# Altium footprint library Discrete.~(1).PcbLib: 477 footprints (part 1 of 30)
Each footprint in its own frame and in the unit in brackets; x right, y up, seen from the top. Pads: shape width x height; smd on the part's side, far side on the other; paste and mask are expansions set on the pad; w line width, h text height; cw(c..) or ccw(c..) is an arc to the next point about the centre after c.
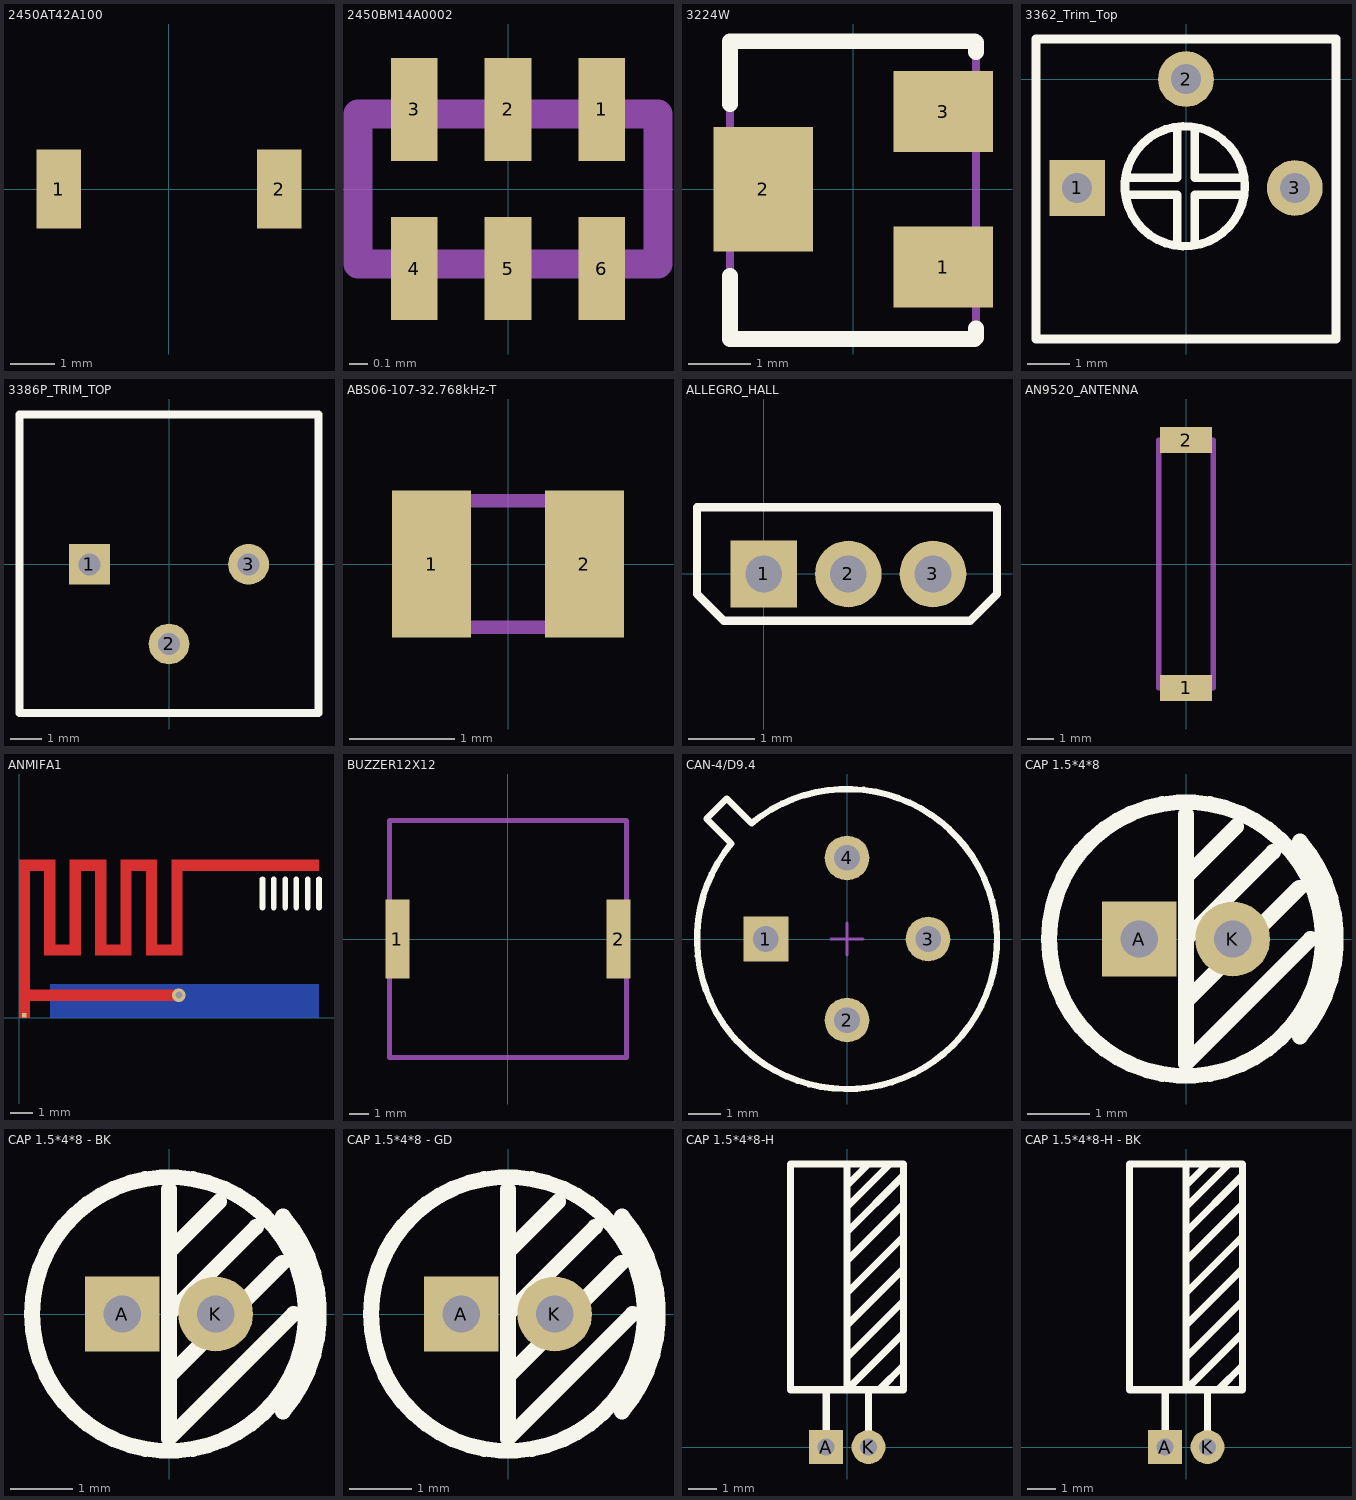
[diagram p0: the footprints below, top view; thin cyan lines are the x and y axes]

## 2450AT42A100 [mm]
pads (2):
  rect 1x1.8 smd: 1(-2.5,0) 2(2.5,0)
3D body: height 1.11, standoff 0, extent -2.1,-0.4 -1.5,0.4
3D body: height 1.1, standoff 0, extent -2.5,-1 2.5,1

## 2450BM14A0002 [mm] "Impedance Matched Balun Filter Integrated Passive for   Nordic’s nRF24L01 and nRF24L01+ Chipsets"
pads (6):
  rect 0.25x0.55 smd: 1(0.5,0.425) 2(0,0.425) 3(-0.5,0.425) 4(-0.5,-0.425) 5(0,-0.425) 6(0.5,-0.425)
Mechanical 13:
  lines w0.152: -0.8,-0.4 0.8,-0.4 0.8,0.4 -0.8,0.4 -0.8,-0.4
3D body: height 0.6, standoff 0, extent -0.8,-0.4 0.8,0.4

## 3224W [mm] "3224 - 4 mm SMD Trimpot"
height 5.1
pads (3):
  rect 1.6x1.3 smd: 1(1.45,-1.25) 3(1.45,1.25)
  rect 1.6x2 smd: 2(-1.45,0)
Top Overlay:
  lines w0.254: -1.98,-1.397 -1.98,-2.408 1.954,-2.408 1.975,-2.388 1.975,-2.235 ; -1.98,1.372 -1.98,2.383 1.954,2.383 1.975,2.362 1.975,2.21
Mechanical 13:
  lines w0.127: -1.98,2.383 1.975,2.383 ; -1.98,-2.408 1.975,-2.408 1.975,2.418 -1.98,2.418 -1.98,-2.408
3D body "SW3dPS-3224W.STEP": height 5.3, standoff 0, extent -1.95,-2.4 1.95,2.4

## 3362_Trim_Top [mm]
pads (3):
  rect 1.3x1.3 hole 0.7: 1(-2.54,-2.54)
  round 1.3 hole 0.7: 2(0,0) 3(2.54,-2.54)
Top Overlay:
  circle w0.2: c-0.028,-2.5 r1.4
  lines w0.2: -1.4,-2.3 -1.1,-2.3 -0.2,-2.3 -0.2,-1.4 -0.2,-1.2 ; -1.3,-2.7 -1.1,-2.7 -0.2,-2.7 -0.2,-3.6 -0.2,-3.8 ; 0.2,-3.8 0.2,-3.6 0.2,-2.7 1.1,-2.7 1.3,-2.7 ; 0.2,-1.2 0.2,-1.4 0.2,-2.3 1.1,-2.3 1.3,-2.3 ; -3.5,-6.065 3.5,-6.065 3.5,0.935 -3.5,0.935 -3.5,-6.065
3D body: height 5, standoff 0, extent -3.5,-6.1 3.5,0.9

## 3386P_TRIM_TOP [mm]
pads (3):
  rect 1.3x1.3 hole 0.7: 1(-2.54,0)
  round 1.3 hole 0.7: 2(0,-2.54) 3(2.54,0)
Top Overlay:
  lines w0.254: -4.765,-4.75 4.765,-4.75 4.765,4.78 -4.765,4.78 -4.765,-4.75
Mechanical 13:
  lines w0.127: -4.788,-4.776 4.788,-4.776 4.788,4.8 -4.788,4.8 -4.788,-4.776
3D body "3386P001XXX.stp": height 5, standoff -5.9, extent -4.788,-4.776 4.788,4.8

## ABS06-107-32.768kHz-T [mm] "SMD Low ESR Crystal"
pads (2):
  rect 0.75x1.4 smd: 1(-0.725,0) 2(0.725,0)
Mechanical 13:
  lines w0.127: -1,-0.6 -1,0.6 1,0.6 1,-0.6 -1,-0.6
3D body: height 0.6, standoff 0, extent -1,-0.6 1,0.6

## ALLEGRO_HALL [mm]
pads (3):
  rect 1x1 hole 0.55 mask+0: 1(0,0)
  round 1 hole 0.55 mask+0: 2(1.27,0) 3(2.54,0)
Top Overlay:
  lines w0.127: -1,0 -1,-0.3 ; -1,-0.3 -0.6,-0.7 3.1,-0.7 3.5,-0.3 3.5,1 -1,1 -1,-0.3

## AN9520_ANTENNA [mm]
pads (2):
  rect 2x1 smd: 1(0,-4.75) 2(0,4.75)
Mechanical 13:
  lines w0.203: -1.05,-4.75 1.05,-4.75 1.05,4.75 -1.05,4.75 -1.05,-4.75
3D body: height 1, standoff 0, extent -1.05,-4.75 1.05,4.75

## ANMIFA1 [mm] "2.4G MIFA 1.6mm Thickness FR4"
pads (1):
  rect 0.2x0.2 smd paste+0 mask+0: 1(0.227,0.113)
via 7.186,1.027 diameter 0.61 hole 0.305
Top Layer:
  region: 13.486,6.62 7.341,6.62 7.341,2.81 5.715,2.81 5.715,6.62 5.055,6.62 5.055,2.81 3.429,2.81 3.429,6.62 2.769,6.62 2.769,2.81 1.143,2.81 1.143,6.62 0.483,6.62 0.483,1.261 7.417,1.261 7.417,0.778 0.483,0.778 0.482,-0.002 0.47,0.003 0,0 0,7.103 1.626,7.103 1.626,3.293 2.286,3.293 2.286,7.103 3.912,7.103 3.912,3.293 4.572,3.293 4.572,7.103 6.198,7.103 6.198,3.293 6.858,3.293 6.858,7.103 13.486,7.103
Bottom Layer:
  rectangle: 1.384,-0.009 13.486,1.515
Top Overlay:
  lines w0.254: 10.946,4.964 10.946,6.234 ; 11.454,4.964 11.454,6.234 ; 11.962,4.964 11.962,6.234 ; 12.47,4.964 12.47,6.234 ; 12.978,4.964 12.978,6.234 ; 13.486,4.964 13.486,6.234

## BUZZER12X12 [mm]
pads (2):
  rect 1.2x4 smd: 1(-5.6,0) 2(5.6,0)
Mechanical 13:
  lines w0.254: -6,-6 -6,6 6,6 6,-6 -6,-6
3D body: height 3, standoff 0, extent -6,-6 6,6

## CAN-4/D9.4 [mm] "Can; 4 Leads; Pin Circle Dia. 5.08 mm; Lead Dia. 0.48 mm (max)"
height 4.7
pads (4):
  rect 1.4x1.4 hole 0.8: 1(-2.54,0)
  round 1.4 hole 0.8: 2(0,-2.54) 3(2.54,0) 4(0,2.54)
Top Overlay:
  lines w0.2: -4.404,3.768 -3.626,2.99 ccw(c0,0) -2.99,3.626 -3.768,4.404 -4.404,3.768
Mechanical 15:
  lines w0.1: -0.5,0 0.5,0 ; 0,-0.5 0,0.5

## CAP 1.5*4*8 [mm] "脚距1.5mm直径4mm高度8mm"
pads (2):
  rect 1.2x1.2 hole 0.6: A(-0.75,0)
  round 1.2 hole 0.6: K(0.75,0)
Top Overlay:
  circle w0.254: c0,0 r2.2
  lines w0.254: 0,-1 1.821,0.821 ; 0,0 1.397,1.397 ; 0,1 0.808,1.808 ; 0,2 0,-2 2,0 ; 1.83,-1.568 ccw(c0,0) 1.83,1.568
3D body "CAP 1.5X4X8.STEP": height 8.04, standoff -3.46, extent -2,-1.999 2.02,1.999

## CAP 1.5*4*8 - BK [mm] "脚距1.5mm直径4mm高度8mm"
pads (2):
  rect 1.2x1.2 hole 0.6: A(-0.75,0)
  round 1.2 hole 0.6: K(0.75,0)
Top Overlay:
  circle w0.254: c0,0 r2.2
  lines w0.254: 0,-1 1.821,0.821 ; 0,0 1.397,1.397 ; 0,1 0.808,1.808 ; 0,2 0,-2 2,0 ; 1.83,-1.568 ccw(c0,0) 1.83,1.568
3D body "CAP 1.5X4X8.STEP": height 8.05, standoff -3.45, extent -2,-1.999 2.02,1.999

## CAP 1.5*4*8 - GD [mm] "脚距1.5mm直径4mm高度8mm"
pads (2):
  rect 1.2x1.2 hole 0.6: A(-0.75,0)
  round 1.2 hole 0.6: K(0.75,0)
Top Overlay:
  circle w0.254: c0,0 r2.2
  lines w0.254: 0,-1 1.821,0.821 ; 0,0 1.397,1.397 ; 0,1 0.808,1.808 ; 0,2 0,-2 2,0 ; 1.83,-1.568 ccw(c0,0) 1.83,1.568
3D body "CAP 1.5X4X8.STEP": height 8.06, standoff -3.44, extent -2,-1.999 2.02,1.999

## CAP 1.5*4*8-H [mm] "脚距1.5mm直径4mm高度8mm"
pads (2):
  rect 1.2x1.2 hole 0.6: A(-0.75,0)
  round 1.2 hole 0.6: K(0.75,0)
Top Overlay:
  lines w0.254: -0.75,0 -0.75,2 ; -0.012,3.175 1.988,5.175 1.988,5.207 ; -0.012,4.318 1.988,6.318 1.988,6.35 ; -0.012,5.461 1.988,7.461 1.988,7.493 ; -0.012,6.604 1.988,8.604 1.988,8.636 ; -0.012,7.62 1.965,9.597 ccw(c1.911,9.652) 1.988,9.652 ; -0.012,8.509 1.51,10.031 cw(c1.512,10.03) 1.512,10.032 ; -0.012,9.271 0.748,10.031 cw(c0.75,10.03) 0.75,10.032 ; -0.012,10.032 -0.012,2.032 ; 0.75,0 0.75,2 ; 0.877,2.921 -0.012,2.032 ; 1.131,2.032 1.988,2.889 1.988,2.921 ; 1.988,4.064 1.988,4.032 -0.012,2.032 ; -2.012,2.032 1.988,2.032 1.988,10.032 -2.012,10.032 -2.012,2.032
3D body "CAP 1.5X4X8-H.STEP": height 4.02, standoff -3.48, extent -2,-0.25 2.02,10

## CAP 1.5*4*8-H - BK [mm] "脚距1.5mm直径4mm高度8mm"
pads (2):
  rect 1.2x1.2 hole 0.6: A(-0.75,0)
  round 1.2 hole 0.6: K(0.75,0)
Top Overlay:
  lines w0.254: -0.75,0 -0.75,2 ; -0.012,3.175 1.988,5.175 1.988,5.207 ; -0.012,4.318 1.988,6.318 1.988,6.35 ; -0.012,5.461 1.988,7.461 1.988,7.493 ; -0.012,6.604 1.988,8.604 1.988,8.636 ; -0.012,7.62 1.965,9.597 ccw(c1.911,9.652) 1.988,9.652 ; -0.012,8.509 1.51,10.031 cw(c1.512,10.03) 1.512,10.032 ; -0.012,9.271 0.748,10.031 cw(c0.75,10.03) 0.75,10.032 ; -0.012,10.032 -0.012,2.032 ; 0.75,0 0.75,2 ; 0.877,2.921 -0.012,2.032 ; 1.131,2.032 1.988,2.889 1.988,2.921 ; 1.988,4.064 1.988,4.032 -0.012,2.032 ; -2.012,2.032 -2.012,10.032 1.988,10.032 1.988,2.032 -2.012,2.032
3D body "CAP 1.5X4X8-H.STEP": height 4.02, standoff -3.48, extent -2,-0.25 2.02,10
